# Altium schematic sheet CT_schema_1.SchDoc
size 461 x 258 mm
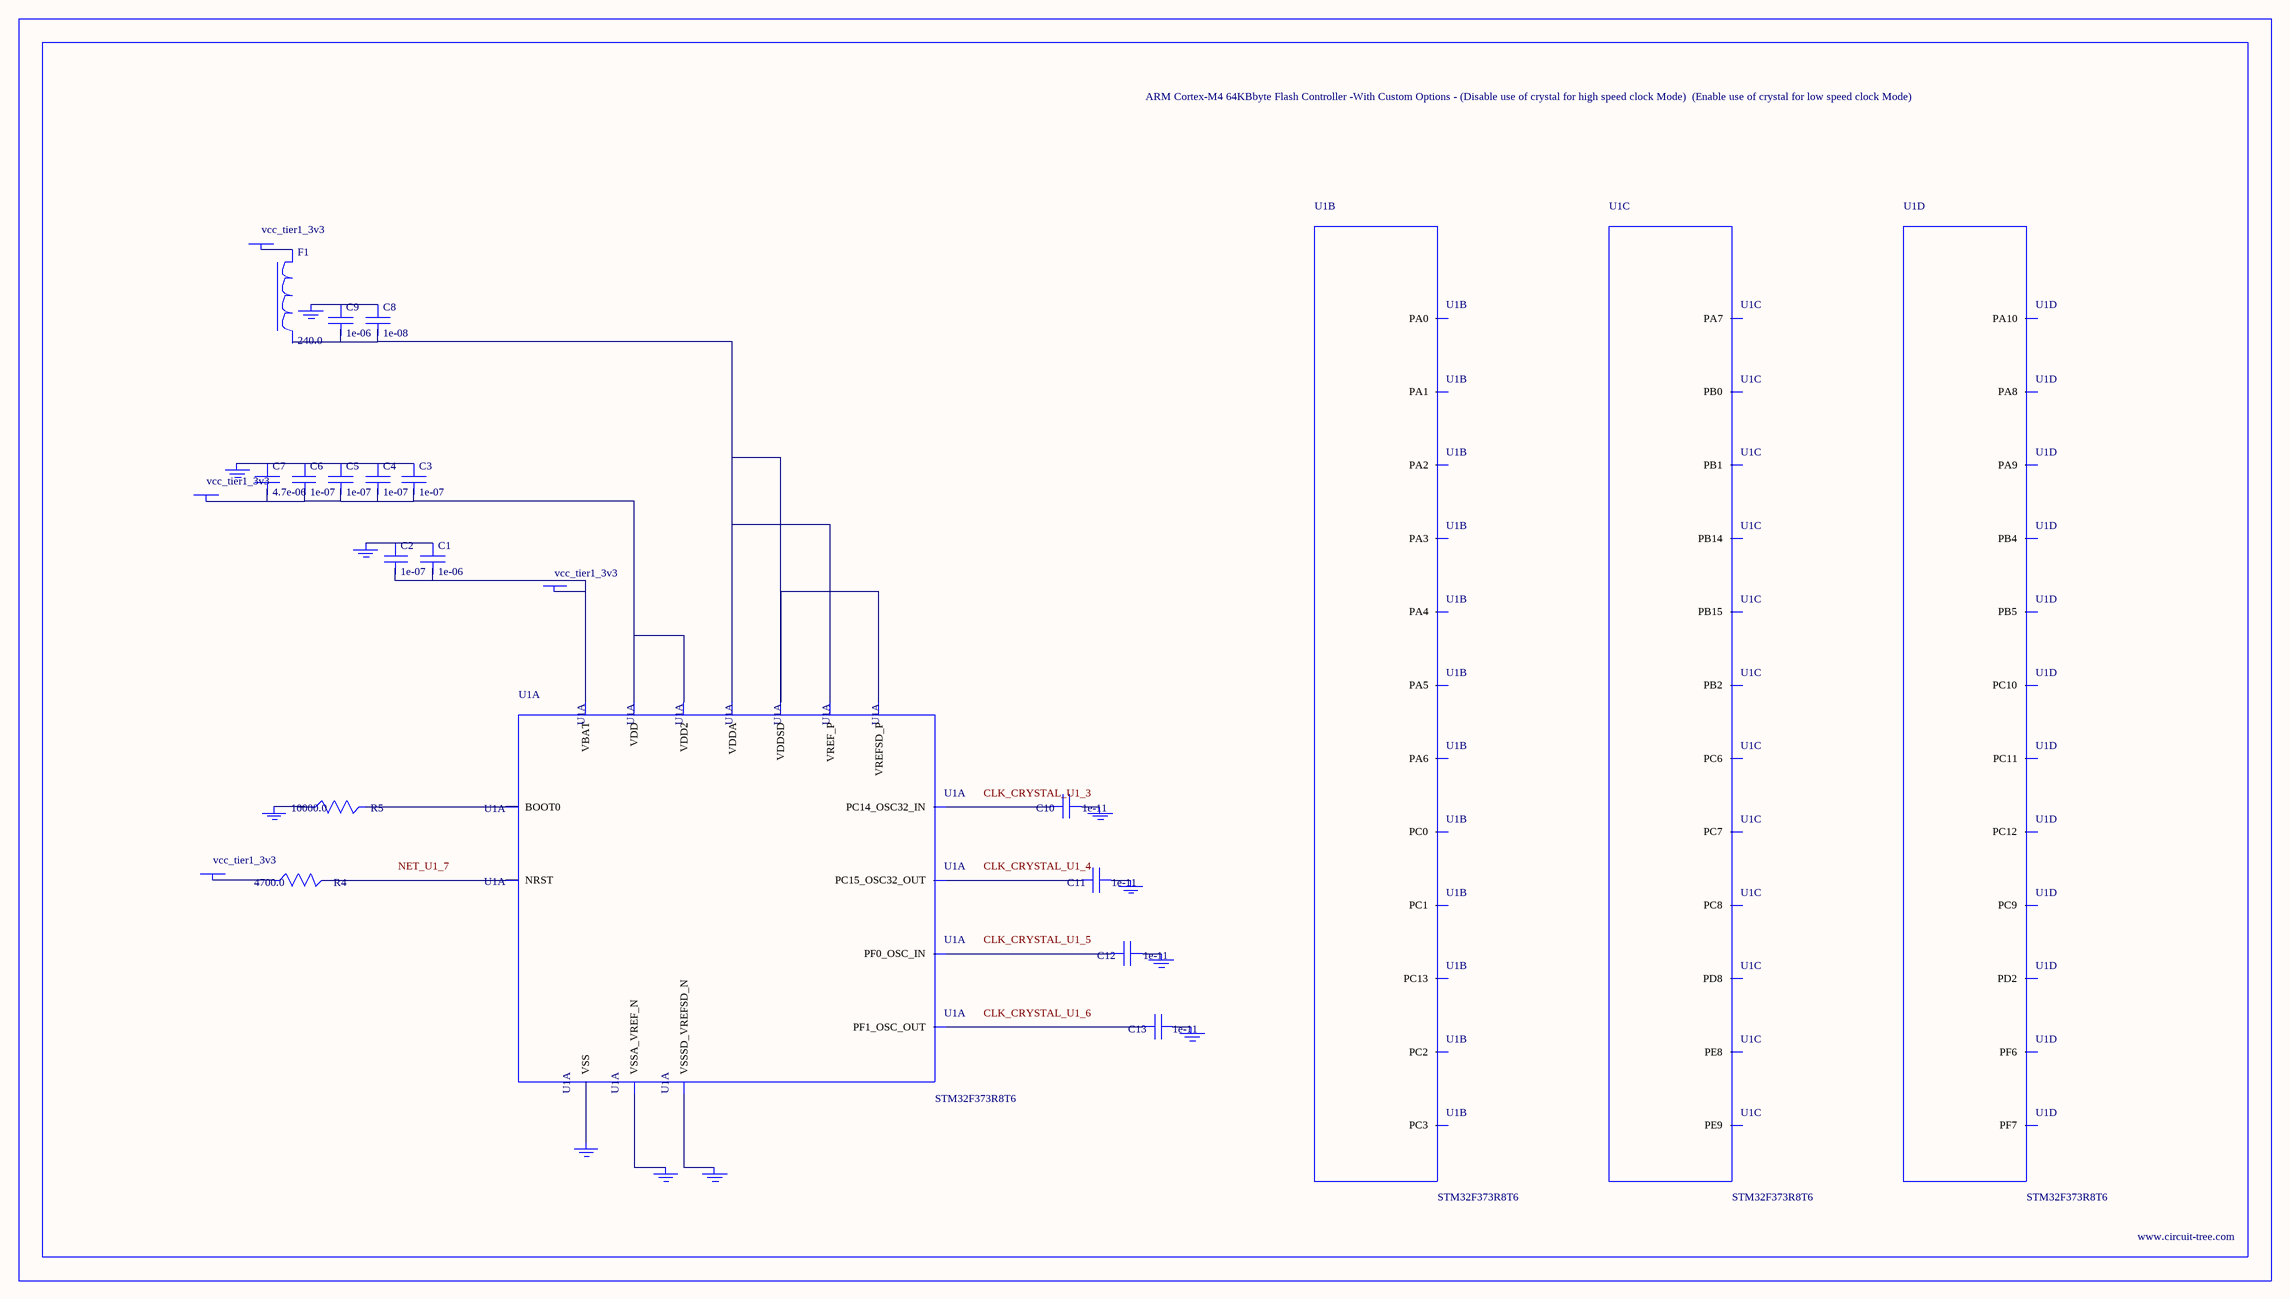
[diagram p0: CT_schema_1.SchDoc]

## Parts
BORDER0  (no value)
C1  1e-06  [C0603]
C2  1e-07  [C0603]
C3  1e-07  [C0603]
C4  1e-07  [C0603]
C5  1e-07  [C0603]
C6  1e-07  [C0603]
C7  4.7e-06  [C0603]
C8  1e-08  [C0603]
C9  1e-06  [C0603]
C10  1e-11  [C0402]
C11  1e-11  [C0402]
C12  1e-11  [C0402]
C13  1e-11  [C0402]
F1  240.0  [L0603]
GND_INSTANCE_0_0  (no value)
GND_INSTANCE_0_1  (no value)
GND_INSTANCE_0_2  (no value)
GND_INSTANCE_0_3  (no value)
GND_INSTANCE_0_4  (no value)
GND_INSTANCE_0_5  (no value)
GND_INSTANCE_0_6  (no value)
GND_INSTANCE_0_7  (no value)
GND_INSTANCE_0_8  (no value)
GND_INSTANCE_0_9  (no value)
GND_INSTANCE_0_10  (no value)
POWER_INSTANCE_0_0  vcc_tier1_3v3
POWER_INSTANCE_0_1  vcc_tier1_3v3
POWER_INSTANCE_0_2  vcc_tier1_3v3
POWER_INSTANCE_0_3  vcc_tier1_3v3
R4  4700.0  [R0603]
R5  10000.0  [R0603]
U1  STM32F373R8T6  [LQFP64]  (parts A,B,C,D of 7)

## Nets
NetC1_1: C1.1 C2.1 GND_INSTANCE_0_0.0(GND)
NetC1_2: C1.2 C2.2 POWER_INSTANCE_0_0.0(PWR) U1.1(VBAT)
NetC3_1: C3.1 C4.1 C5.1 C6.1 C7.1 GND_INSTANCE_0_7.0(GND)
NetC3_2: C3.2 C4.2 C5.2 C6.2 C7.2 POWER_INSTANCE_0_2.0(PWR) U1.19(VDD) U1.64(VDD2)
NetC8_1: C8.1 C9.1 GND_INSTANCE_0_6.0(GND)
NetC8_2: C8.2 C9.2 U1.13(VDDA) U1.17(VREF_P) U1.32(VDDSD) U1.33(VREFSD_P)
NetC10_1: C10.1 GND_INSTANCE_0_1.0(GND)
NetC10_2: C10.2 U1.3(PC14_OSC32_IN)
NetC11_1: C11.1 GND_INSTANCE_0_2.0(GND)
NetC11_2: C11.2 U1.4(PC15_OSC32_OUT)
NetC12_1: C12.1 GND_INSTANCE_0_3.0(GND)
NetC12_2: C12.2 U1.5(PF0_OSC_IN)
NetC13_1: C13.1 GND_INSTANCE_0_4.0(GND)
NetC13_2: C13.2 U1.6(PF1_OSC_OUT)
NetF1_1: F1.1 POWER_INSTANCE_0_1.0(PWR)
NetGND_INSTANCE_0_5_0: GND_INSTANCE_0_5.0(GND) U1.12(VSSA_VREF_N)
NetGND_INSTANCE_0_8_0: GND_INSTANCE_0_8.0(GND) U1.31(VSSSD_VREFSD_N)
NetGND_INSTANCE_0_9_0: GND_INSTANCE_0_9.0(GND) R5.1
NetGND_INSTANCE_0_10_0: GND_INSTANCE_0_10.0(GND) U1.63(VSS)
NetPOWER_INSTANCE_0_3_0: POWER_INSTANCE_0_3.0(PWR) R4.1
NetR4_2: R4.2 U1.7(NRST)
NetR5_2: R5.2 U1.60(BOOT0)

Not connected (* = marked no-connect by the designer): F1 2; U1 2(PC13) 8(PC0) 9(PC1) 10(PC2) 11(PC3) 14(PA0) 15(PA1) 16(PA2) 18(PA3) 20(PA4) 21(PA5) 22(PA6) 23(PA7) 26(PB0) 27(PB1) 28(PB2) 29(PE8) 30(PE9) 34(PB14) 35(PB15) 36(PD8) 37(PC6) 38(PC7) 39(PC8) 40(PC9) 41(PA8) 42(PA9) 43(PA10) 47(PF6) 48(PF7) 51(PC10) 52(PC11) 53(PC12) 54(PD2) 56(PB4) 57(PB5)

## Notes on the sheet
- Labels drawn without touching a wire or pin: CLK_CRYSTAL_U1_3, CLK_CRYSTAL_U1_4, CLK_CRYSTAL_U1_5, CLK_CRYSTAL_U1_6, NET_U1_7

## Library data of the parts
BORDER0 = BORDER_PAGE0
C1 C9 = C0603C105K3RACTU
C2-C6 = 06035C104K4Z2A
C7 = GRM188R6YA475KE15D
C8 = 06035C103K4Z2A
C10-C13 = C0402C100K3GACTU
F1 = Z0603C241ASMST
GND_INSTANCE_0_0-GND_INSTANCE_0_10 = GND
POWER_INSTANCE_0_0-POWER_INSTANCE_0_3 = PWR
R4 = RC0603JR-074K7L
R5 = RC0603JR-0710KL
